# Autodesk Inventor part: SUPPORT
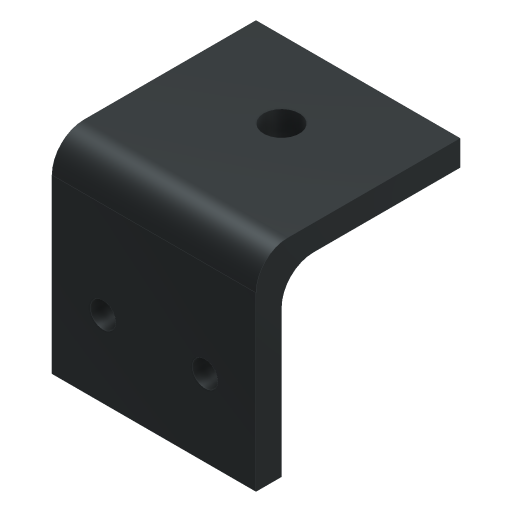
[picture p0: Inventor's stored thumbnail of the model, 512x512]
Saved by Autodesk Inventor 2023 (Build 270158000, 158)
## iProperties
Created: 2016-05
Part Number: SUPPORT
Material: Iron, Cast
Document SubType Name: Modeling
Designer: CADCIM
Density: 7.15 g/cm^3
Appearance: Iron Gray
Mass: 104.47 g
Surface Area: 70.4692 cm^2
Volume: 14.6112 cm^3
Author: CADCIM
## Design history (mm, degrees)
sketch "Sketch1"
  geometry: L1 (0, 0)-(40, 0); L2 (40, 0)-(40, -5); L3 (40, -5)-(5, -5); L4 (5, -5)-(5, -40); L5 (5, -40)-(0, -40); L6 (0, -40)-(0, 0)
  constraints: 12 end point, 2 parallel, 2 perpendicular, 1 horizontal
  dimensions: "d2" = 40 distance between parallel lines of L6 L2; "d3" = 40 distance of L5.end L1.start; "d4" = 5 distance between parallel lines of L1 L3
extrude "Extrusion1" new body sketch "Sketch1" distance "d0" = 40; taper "d1" = 0 deg
sketch "Sketch2"
  geometry: L1 (0, 0)-(0, 35) reference; L2 (0, 35)-(-40, 35) reference; C1 r 3.5 at (-20, 20); 1 further point
  constraints: 1 centre point
  dimensions: "d5" = 7 diameter of C1; "d6" = 20 distance from line of C1.centre L1; "d7" = 15 distance from line of L2 C1.centre
extrude "Extrusion2" cut sketch "Sketch2" distance "d8" = 40; taper "d9" = 0 deg
sketch "Sketch3"
  geometry: L1 (40, 35)-(40, 0) reference; L2 (0, 35)-(40, 35) reference; C1 r 2.5 at (10, 20); C2 r 2.5 at (30, 20); 1 further point
  constraints: 2 centre point, 1 equal radius, 1 horizontal alignment
  dimensions: "d10" = 20 distance of C2.centre C1.centre; "d11" = 10 distance from line of L1 C2.centre; "d12" = 15 distance from line of L2 C2.centre; "d13" = 5 diameter of C1
extrude "Extrusion3" cut sketch "Sketch3" distance "d14" = 40; taper "d15" = 0 deg
fillet "Fillet1" dims "d16" = 6.25
body "Solid1"
